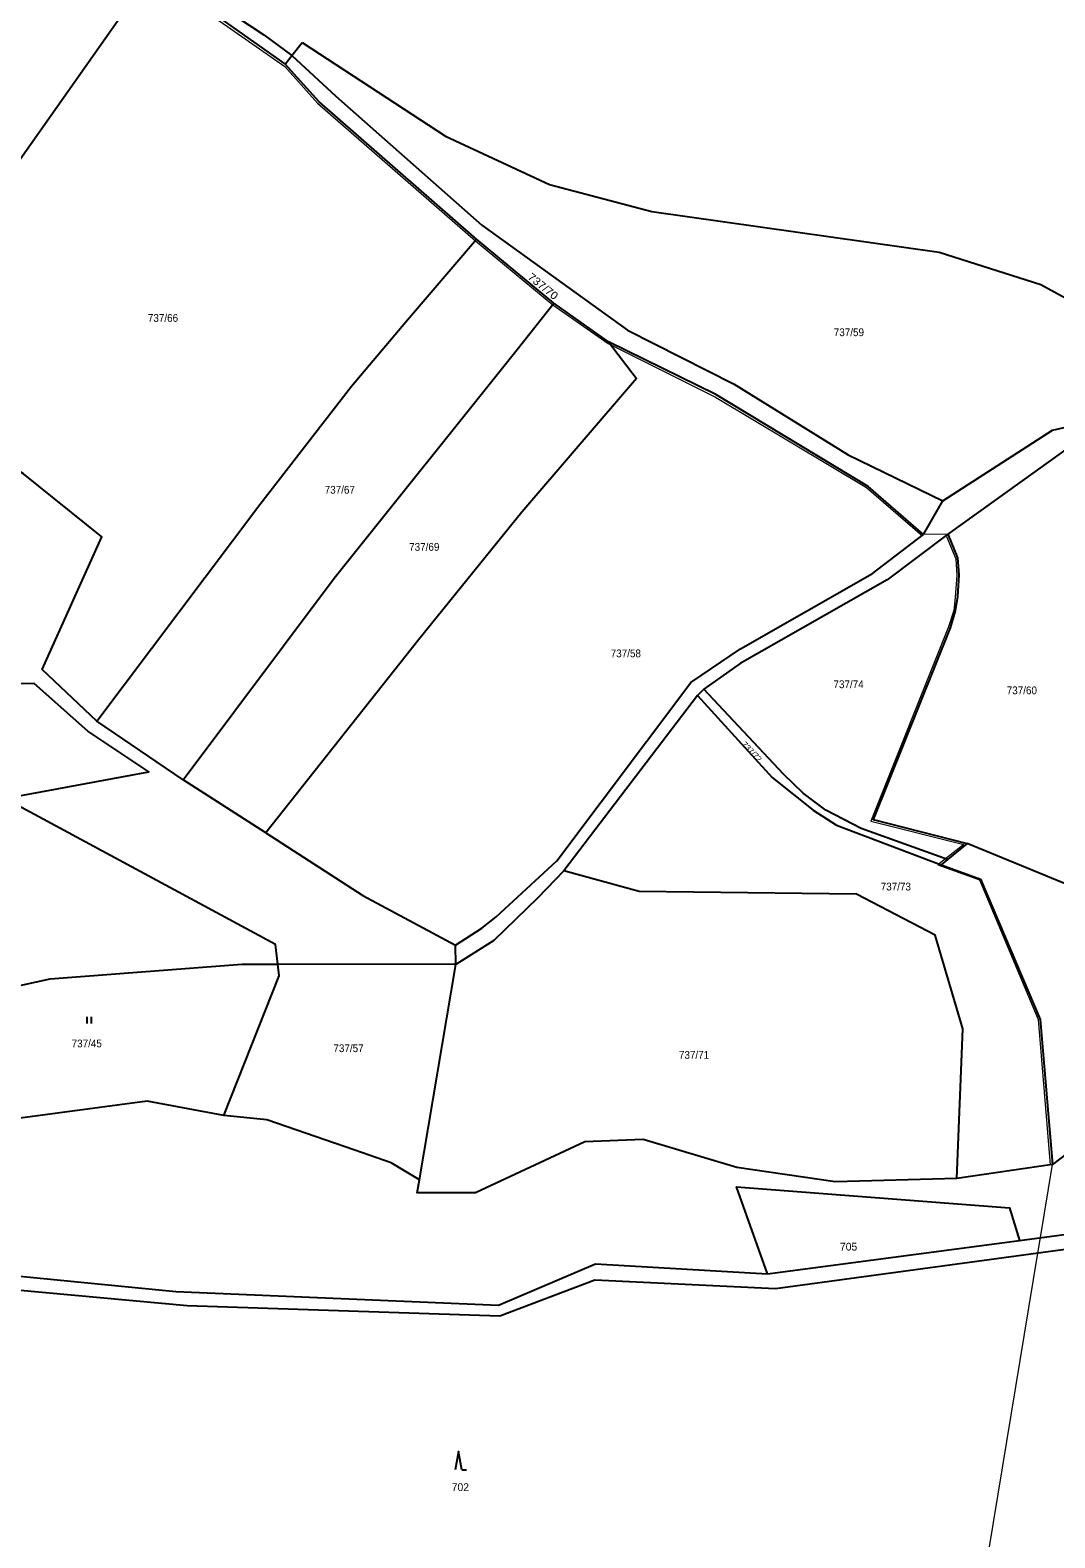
# Model space of a CAD drawing. Extents: x -687135 to -684370, y -1007309 to -1005782.
# Drawn here: x -686364.9 to -686141.1, y -1006769.6 to -1006440.4 of the extents above; entities that cross this region are included whole.
import ezdxf

# ---------------------------------------------------------------- set-up
doc = ezdxf.new("R2010")
doc.units = 0
doc.header["$LTSCALE"] = 0.68
for name, color, linetype, lineweight in [('1', 7, 'Continuous', 25), ('3', 7, 'Continuous', 25), ('4', 7, 'Continuous', 13)]:
    doc.layers.add(name, color=color, linetype=linetype, lineweight=lineweight)
doc.layers.add('2', color=7, linetype='Continuous')

msp = doc.modelspace()

# ---------------------------------------------------------------- linework, layer by layer
at = {"layer": '1'}
for p, q in [((-686238.6, -1006508.44), (-686250.57, -1006499.98)), ((-686169.8, -1006550.53), (-686165.61, -1006543.15)), ((-686217.83, -1006584.31), (-686219.21, -1006585.69)), ((-686219.21, -1006585.69), (-686248.4, -1006623.93)), ((-686271.94, -1006644.43), (-686272.04, -1006640.16)), ((-686203.86, -1006711.97), (-686148.89, -1006704.67))]:
    msp.add_line(p, q, dxfattribs=at)
for points in [[(-686561.24, -1006368.14), (-686522.87, -1006370.66), (-686481.95, -1006372.54), (-686457.01, -1006376.26), (-686416.2, -1006386.98), (-686383.04, -1006398.91), (-686343.13, -1006422.02), (-686313.86, -1006441.37), (-686307.75, -1006445.89), (-686305.49, -1006443.04)], [(-686474.82, -1006470.5), (-686400.67, -1006516.06), (-686338.16, -1006427.36)], [(-686338.16, -1006427.36), (-686309.22, -1006447.79), (-686307.75, -1006445.89)], [(-686984.76, -1006428.31), (-686969.57, -1006429.7), (-686934.19, -1006429.13), (-686907.35, -1006435.05), (-686851.6, -1006457.67), (-686817.92, -1006486.94), (-686781.69, -1006496.55), (-686760.9, -1006489.89), (-686724.99, -1006485.24), (-686692.9, -1006493.7), (-686661.95, -1006520.83), (-686640.73, -1006554.73), (-686599.57, -1006601.79), (-686576.51, -1006619.5), (-686545.07, -1006654.9), (-686452.7, -1006711.84), (-686422.4, -1006717.6), (-686386.45, -1006710.61), (-686333.13, -1006715.82), (-686262.62, -1006718.78), (-686241.47, -1006709.79), (-686203.86, -1006711.97)], [(-686305.49, -1006443.04), (-686274.23, -1006463.55), (-686251.47, -1006474.12), (-686229.17, -1006479.96), (-686166.37, -1006488.85)], [(-686307.75, -1006445.89), (-686298.15, -1006454.81), (-686266.25, -1006482.97), (-686234.45, -1006505.89), (-686211.15, -1006517.72), (-686186.28, -1006533.09), (-686165.61, -1006543.15)], [(-686267.47, -1006486.04), (-686301.78, -1006456.01), (-686309.22, -1006447.79)], [(-686350.38, -1006591.28), (-686314.77, -1006543.96), (-686294.77, -1006518.13), (-686282.54, -1006503.63), (-686267.47, -1006486.04)], [(-686331.48, -1006604.1), (-686298.56, -1006560.06), (-686258.57, -1006510.14), (-686250.57, -1006499.98), (-686267.47, -1006486.04)], [(-686166.37, -1006488.85), (-686144.21, -1006495.9), (-686124.64, -1006506.61)], [(-686238.6, -1006508.44), (-686232.54, -1006516.45), (-686257.54, -1006545.65), (-686280.05, -1006573.43), (-686313.47, -1006615.66)], [(-686169.8, -1006550.53), (-686181.94, -1006540.02), (-686215.15, -1006519.96), (-686238.6, -1006508.44)], [(-686350.38, -1006591.28), (-686362.33, -1006580), (-686349.27, -1006551.01), (-686366.38, -1006537.29), (-686400.67, -1006516.06)], [(-686165.61, -1006543.15), (-686141.63, -1006527.76), (-686124.38, -1006523.77), (-686119.97, -1006523.43), (-686102.38, -1006524.64), (-686084.53, -1006528.55), (-686087.98, -1006526.66), (-686093.28, -1006523.76)], [(-686102.13, -1006529.45), (-686114.72, -1006528.31), (-686125.17, -1006527.56), (-686139.22, -1006532.34), (-686164.52, -1006550.47)], [(-686272.04, -1006640.16), (-686266.3, -1006636.51), (-686263.17, -1006633.99), (-686249.9, -1006621.76), (-686220.63, -1006582.84), (-686209.78, -1006575.48), (-686180.95, -1006559.04), (-686169.8, -1006550.53)], [(-686164.52, -1006550.47), (-686177.77, -1006560.39), (-686209.83, -1006578.72), (-686217.83, -1006584.31)], [(-686164.52, -1006550.47), (-686162.42, -1006555.6), (-686162.11, -1006559.3), (-686162.42, -1006564.09), (-686162.89, -1006567.18), (-686163.97, -1006570.88), (-686180.79, -1006612.72), (-686160.31, -1006617.98)], [(-685878.5, -1006732.89), (-685928.73, -1006713.6), (-685975.55, -1006716.87), (-685988.08, -1006722.32), (-686011.25, -1006727.78), (-686034.41, -1006726.41), (-686082.84, -1006705.15), (-686115.81, -1006703.51), (-686202.12, -1006715.24), (-686241.64, -1006713.33), (-686262.35, -1006721.24), (-686330.66, -1006718.97), (-686386.9, -1006713.77), (-686422.4, -1006720.35), (-686454.83, -1006714.05), (-686546.04, -1006658.04), (-686579.08, -1006621.42), (-686600.54, -1006604.47), (-686642.63, -1006556.52)], [(-686370.47, -1006608.19), (-686339, -1006602.36), (-686352.33, -1006593.47), (-686364.06, -1006583.04), (-686414.94, -1006584.24)], [(-686164.6, -1006621.5), (-686183.41, -1006614.75), (-686191.13, -1006610.73), (-686196.07, -1006607.03), (-686200.39, -1006602.86), (-686217.83, -1006584.31)], [(-686219.21, -1006585.69), (-686202.86, -1006603.61), (-686193.91, -1006610.72), (-686188.81, -1006613.96), (-686165.98, -1006622.63)], [(-686313.47, -1006615.66), (-686331.48, -1006604.1), (-686350.38, -1006591.28)], [(-686310.84, -1006644.34), (-686311.36, -1006640.03), (-686370.47, -1006608.19)], [(-686313.47, -1006615.66), (-686292.28, -1006629.36), (-686272.04, -1006640.16)], [(-686109.9, -1006654.03), (-686132.98, -1006629.22), (-686140.6, -1006626.09), (-686160.31, -1006617.98), (-686164.6, -1006621.5), (-686165.98, -1006622.63)], [(-686248.4, -1006623.93), (-686254.06, -1006629.83), (-686263.63, -1006639.14), (-686271.94, -1006644.43)], [(-686162.53, -1006691.14), (-686161.25, -1006658.49), (-686167.25, -1006638.03), (-686184.46, -1006629.07), (-686231.89, -1006628.48), (-686248.4, -1006623.93)], [(-686165.98, -1006622.63), (-686157.37, -1006625.77), (-686144.32, -1006656.43), (-686141.68, -1006688.12)], [(-686391.1, -1006654.24), (-686360.59, -1006647.58), (-686318.67, -1006644.32), (-686310.84, -1006644.34)], [(-686322.66, -1006677.37), (-686310.53, -1006646.92), (-686310.84, -1006644.34)], [(-686279.88, -1006691.44), (-686271.94, -1006644.43), (-686310.84, -1006644.34)], [(-686084.96, -1006664.73), (-686094.77, -1006661.56), (-686117.7, -1006655.37), (-686119.66, -1006671.37), (-686141.68, -1006688.12), (-686162.53, -1006691.14)], [(-686322.66, -1006677.37), (-686339.37, -1006674.28), (-686378.58, -1006679.53)], [(-686279.88, -1006691.44), (-686286.11, -1006687.72), (-686294, -1006684.97), (-686313.24, -1006678.34), (-686322.66, -1006677.37)], [(-686162.53, -1006691.14), (-686189.12, -1006691.9), (-686210.57, -1006688.71), (-686231.02, -1006682.61), (-686243.8, -1006683.17), (-686267.66, -1006694.25), (-686280.43, -1006694.25), (-686279.88, -1006691.44)], [(-686203.86, -1006711.97), (-686210.67, -1006692.97), (-686151.05, -1006697.52), (-686148.89, -1006704.67)], [(-686148.89, -1006704.67), (-686115.65, -1006700.25), (-686083.22, -1006702.43), (-686034.44, -1006722.6), (-686012.09, -1006723.97), (-685989.74, -1006719.06), (-685976.47, -1006713.34), (-685928.51, -1006710.34), (-685876.62, -1006730.81), (-685866.37, -1006705.16)]]:
    msp.add_lwpolyline(points, dxfattribs=at)
at = {"layer": '3'}
for p, q in [((-686352.501, -1006657.32), (-686352.501, -1006655.82)), ((-686351.5, -1006657.32), (-686351.5, -1006655.82)), ((-686270.63, -1006754.75), (-686269.634, -1006754.75))]:
    msp.add_line(p, q, dxfattribs=at)
msp.add_lwpolyline([(-686270.63, -1006754.75), (-686271.38, -1006750.75), (-686272.13, -1006754.75)], dxfattribs=at)
at = {"layer": '4'}
for p in [(-686164.53, -1006550.47), (-686164.52, -1006550.47)]:
    msp.add_line(p, (-686169.8, -1006550.53), dxfattribs=at)
for points in [[(-686457.7, -1006378), (-686454.32, -1006379.02), (-686419.16, -1006388.76), (-686384.15, -1006401.63), (-686338.41, -1006427.9), (-686309.29, -1006448.3), (-686302.18, -1006456.36), (-686267.7, -1006486.42), (-686250.8, -1006500.38), (-686238.72, -1006508.83), (-686215.25, -1006520.51), (-686182.24, -1006540.24), (-686170.03, -1006550.84)], [(-686164.8, -1006550.97), (-686162.79, -1006555.8), (-686162.52, -1006559.43), (-686162.92, -1006564.26), (-686163.19, -1006567.08), (-686164.4, -1006570.7), (-686181.3, -1006613.11), (-686161.04, -1006618.21), (-686166.68, -1006622.64), (-686157.59, -1006625.96), (-686144.81, -1006656.46), (-686142.13, -1006688.13)], [(-686156.08, -1006775.56), (-686155.5, -1006772.03), (-686144.87, -1006707.46), (-686144.31, -1006704.06), (-686141.68, -1006688.12)]]:
    msp.add_lwpolyline(points, dxfattribs=at)

# ---------------------------------------------------------------- texts
at = {"layer": '2', "width": 1.1}
for s, height, rotation, p in [('737/70', 1.7, 321, (-686256.424, -1006494.57)), ('737/72', 1.19, 314, (-686209.578, -1006596.413))]:
    msp.add_text(s, height=height, rotation=rotation, dxfattribs=at).set_placement(p)
at = {"layer": '2', "width": 0.95}
for s, p in [('737/66', (-686339.22, -1006504.07)), ('737/59', (-686189.42, -1006507.2)), ('737/67', (-686300.6, -1006541.6)), ('737/69', (-686282.16, -1006554.07)), ('737/58', (-686238.14, -1006577.33)), ('737/74', (-686189.49, -1006584.07)), ('737/60', (-686151.65, -1006585.4)), ('737/73', (-686179.17, -1006628.25)), ('737/45', (-686355.87, -1006662.51)), ('737/57', (-686298.7, -1006663.549)), ('737/71', (-686223.24, -1006665))]:
    msp.add_text(s, height=1.7, dxfattribs=at).set_placement(p)
at = {"layer": '2'}
for s, p in [('705', (-686188.08, -1006706.88)), ('702', (-686272.87, -1006759.4))]:
    msp.add_text(s, height=1.7, dxfattribs=at).set_placement(p)

doc.saveas('drawing.dxf')
